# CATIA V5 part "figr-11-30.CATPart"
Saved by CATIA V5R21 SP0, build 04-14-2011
Part number: Part1
Bounding box of the stored display mesh (mm): x -205 to 53, y -75.374 to 75.374, z 0 to 37.54
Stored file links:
  D:\CATIA V5R21 E-RESOURCES\CATIA-V5R21\catia-v5r21-prt\c11-catia-v5r21-prt\c11-catia-v5r21-figr-11-30.CATPart
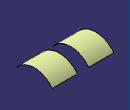
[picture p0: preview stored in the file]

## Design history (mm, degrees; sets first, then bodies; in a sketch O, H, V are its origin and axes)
Set1
  Extrude1: Element1 Sketch1, Lim1 53, Lim2 52, Direction yz-plane
  Translate1: ToTransfor Extrude1, Direction edge of Extrude1, Length 153
Body1 (main body)
  Sketch1 on yz-plane, origin (0, 0, 0), H (0, 1, 0), V (0, 0, 1)
    arc A1 centre (0, -56.4477) radius 94.1675 from (-75.3736, 0) to (75.3736, 0) cw
    point P1 (0, -56.4477)
    point P2 (-75.3736, 0)
    point P3 (75.3736, 0)
    point P4 (0, 37.7198)
    coincidence: P2 H, P3 H, A1 P4, P4 V, P1 V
